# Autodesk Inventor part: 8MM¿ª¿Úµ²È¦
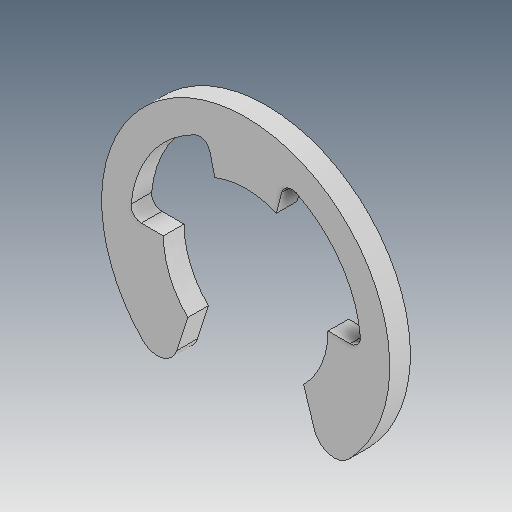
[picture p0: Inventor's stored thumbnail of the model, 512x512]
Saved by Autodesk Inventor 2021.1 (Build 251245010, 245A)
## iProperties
Created: 2019-04
Part Number: 8MM¿ª¿Úµ²È¦
Material: Ogólny
Document SubType Name: Modeling
Designer: user
Density: 1 g/cm^3
Appearance: Domyślna
Author: user
Revision Number: ÈÎºÎ
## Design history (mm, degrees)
feature "ÊäÈë1"
node "Bryła1"
